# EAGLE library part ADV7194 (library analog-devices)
Professional Extended-10 (TM) Video Encoder with 54 MHz Oversampling Auto generated by make-symbol-device-package-bsdl.ulp Rev. 33 Source: http://www.analog.com/static/imported-files/data_sheets/ADV7194.pdf
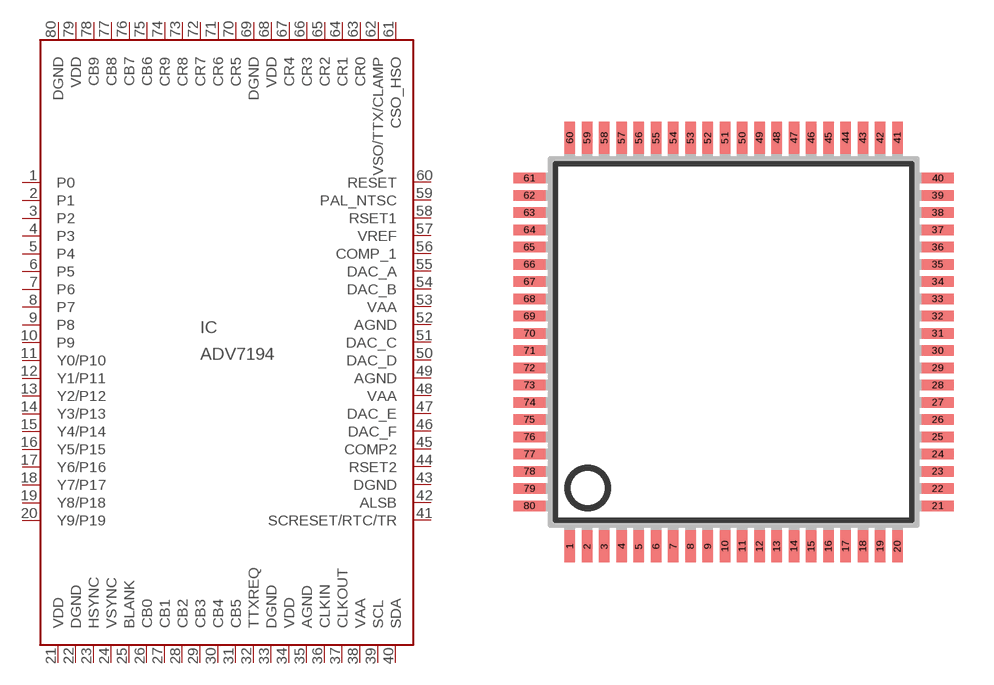
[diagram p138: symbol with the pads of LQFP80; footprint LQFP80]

Designator prefix IC

## ADV7194 (MPN: ADV7194KSTZ; OC_FARNELL: 1438743; OC_NEWARK: 39P9724)  [LQFP80]
1  P0  in
2  P1  in
3  P2  in
4  P3  in
5  P4  in
6  P5  in
7  P6  in
8  P7  in
9  P8  in
10  P9  in
11  Y0/P10  in
12  Y1/P11  in
13  Y2/P12  in
14  Y3/P13  in
15  Y4/P14  in
16  Y5/P15  in
17  Y6/P16  in
18  Y7/P17  in
19  Y8/P18  in
20  Y9/P19  in
21  VDD  pwr
22  DGND  pwr
23  HSYNC
24  VSYNC
25  BLANK
26  CB0  in
27  CB1  in
28  CB2  in
29  CB3  in
30  CB4  in
31  CB5  in
32  TTXREQ  out
33  DGND  pwr
34  VDD  pwr
35  AGND  pwr
36  CLKIN  in
37  CLKOUT  out
38  VAA  pwr
39  SCL  in
40  SDA
41  SCRESET/RTC/TR  in
42  ALSB  in
43  DGND  pwr
44  RSET2  in
45  COMP2  out
46  DAC_F  out
47  DAC_E  out
48  VAA  pwr
49  AGND  pwr
50  DAC_D  out
51  DAC_C  out
52  AGND  pwr
53  VAA  pwr
54  DAC_B  out
55  DAC_A  out
56  COMP_1  out
57  VREF
58  RSET1  in
59  PAL_NTSC  in
60  RESET  in
61  CSO_HSO  out
62  VSO/TTX/CLAMP
63  CR0  in
64  CR1  in
65  CR2  in
66  CR3  in
67  CR4  in
68  VDD  pwr
69  DGND  pwr
70  CR5  in
71  CR6  in
72  CR7  in
73  CR8  in
74  CR9  in
75  CB6  in
76  CB7  in
77  CB8  in
78  CB9  in
79  VDD  pwr
80  DGND  pwr

## Footprint LQFP80 (pad centres in mm)
80 Lead LQFP_ED (SQ-80) (ST-80) Source: www.analog.com .. AD9852_b.pdf
smd 0.4 x 1.2: 1 -6.175,-7.7; 2 -5.525,-7.7; 3 -4.875,-7.7; 4 -4.225,-7.7; 5 -3.575,-7.7; 6 -2.925,-7.7; 7 -2.275,-7.7; 8 -1.625,-7.7; 9 -0.975,-7.7; 10 -0.325,-7.7; 11 0.325,-7.7; 12 0.975,-7.7; 13 1.625,-7.7; 14 2.275,-7.7; 15 2.925,-7.7; 16 3.575,-7.7; 17 4.225,-7.7; 18 4.875,-7.7; 19 5.525,-7.7; 20 6.175,-7.7; 41 6.175,7.7; 42 5.525,7.7; 43 4.875,7.7; 44 4.225,7.7; 45 3.575,7.7; 46 2.925,7.7; 47 2.275,7.7; 48 1.625,7.7; 49 0.975,7.7; 50 0.325,7.7; 51 -0.325,7.7; 52 -0.975,7.7; 53 -1.625,7.7; 54 -2.275,7.7; 55 -2.925,7.7; 56 -3.575,7.7; 57 -4.225,7.7; 58 -4.875,7.7; 59 -5.525,7.7; 60 -6.175,7.7
smd 1.2 x 0.4: 21 7.7,-6.175; 22 7.7,-5.525; 23 7.7,-4.875; 24 7.7,-4.225; 25 7.7,-3.575; 26 7.7,-2.925; 27 7.7,-2.275; 28 7.7,-1.625; 29 7.7,-0.975; 30 7.7,-0.325; 31 7.7,0.325; 32 7.7,0.975; 33 7.7,1.625; 34 7.7,2.275; 35 7.7,2.925; 36 7.7,3.575; 37 7.7,4.225; 38 7.7,4.875; 39 7.7,5.525; 40 7.7,6.175; 61 -7.7,6.175; 62 -7.7,5.525; 63 -7.7,4.875; 64 -7.7,4.225; 65 -7.7,3.575; 66 -7.7,2.925; 67 -7.7,2.275; 68 -7.7,1.625; 69 -7.7,0.975; 70 -7.7,0.325; 71 -7.7,-0.325; 72 -7.7,-0.975; 73 -7.7,-1.625; 74 -7.7,-2.275; 75 -7.7,-2.925; 76 -7.7,-3.575; 77 -7.7,-4.225; 78 -7.7,-4.875; 79 -7.7,-5.525; 80 -7.7,-6.175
